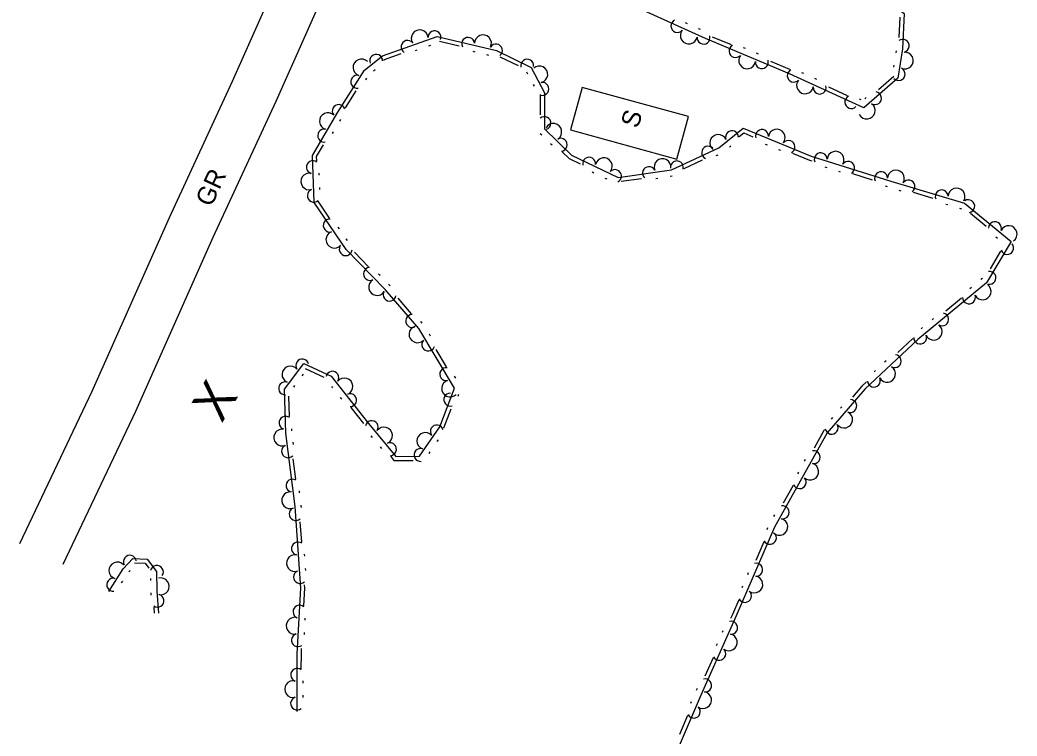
# Model space of a CAD drawing. Extents: x 2030130 to 2036320, y 723205 to 762423.
# Drawn here: x 2032510.8 to 2032711.2, y 760341.1 to 760485 of the extents above; entities that cross this region are included whole.
import ezdxf

# ---------------------------------------------------------------- set-up
doc = ezdxf.new("R2010")
doc.units = 0
for name, color, linetype in [('Draft_Station Labels Major', 7, 'Continuous'), ('Draft_Station Tics Major', 7, 'Continuous'), ('Exist Terrain Model Ground Surface', 7, 'Continuous'), ('Old_Level_23', 7, 'Continuous'), ('Old_Level_28', 7, 'Continuous')]:
    doc.layers.add(name, color=color, linetype=linetype)

msp = doc.modelspace()

# ---------------------------------------------------------------- linework, layer by layer
at = {"layer": 'Draft_Station Labels Major'}
for points in [[(2032510.76, 760379.73), (2032525.28, 760410.37), (2032540.81, 760445.33), (2032553.46, 760472.68), (2032565.25, 760499.26), (2032573.55, 760520.99), (2032582.53, 760547.1)], [(2032519.47, 760375.6), (2032534.05, 760406.34), (2032549.6, 760441.35), (2032562.24, 760468.7), (2032574.17, 760495.58), (2032582.62, 760517.7), (2032591.65, 760543.96)]]:
    msp.add_lwpolyline(points, dxfattribs=at)
at = {"layer": 'Draft_Station Tics Major'}
for points in [[(2032610.36, 760505.83), (2032617.7, 760509.06), (2032625.07, 760510.08), (2032635.55, 760509.05), (2032646.26, 760506.58), (2032658.84, 760502.68), (2032665.92, 760499.68), (2032681.91, 760491.35), (2032688.45, 760486.32), (2032688.15, 760479.19), (2032687.21, 760473.29), (2032680.34, 760467.34), (2032665.41, 760474.21), (2032648.54, 760481.27), (2032632.66, 760488.42), (2032618.48, 760493.45), (2032608.94, 760497.68), (2032607.53, 760501.46), (2032610.14, 760506.24)], [(2032687.6, 760485.58), (2032687.42, 760481.49)], [(2032644.9, 760484.26), (2032644.53, 760484.42)], [(2032647.52, 760483.08), (2032647.15, 760483.25)], [(2032566.45, 760345.97), (2032566.49, 760357.61), (2032567.18, 760370.77), (2032566.07, 760387.21), (2032564.19, 760401.97), (2032563.93, 760410.79), (2032567.82, 760415.97), (2032573.31, 760413.37), (2032580.84, 760403.88), (2032586.31, 760397.28), (2032591.09, 760397.29), (2032595.17, 760403.2), (2032598.11, 760411.01), (2032590.92, 760422.96), (2032584.18, 760430.79), (2032576.3, 760438.86), (2032569.87, 760448.28), (2032569.56, 760457.75), (2032574.67, 760466.46), (2032580.02, 760474.93), (2032583.62, 760477.8), (2032594.58, 760481.69), (2032606.53, 760478.85), (2032613.5, 760475.44), (2032616.15, 760470.39), (2032616.17, 760463.09), (2032621.61, 760457.81), (2032630.96, 760453.33), (2032641.69, 760454.86), (2032651.22, 760459.33), (2032656.11, 760463.24), (2032669.75, 760457.6), (2032685.78, 760452.57), (2032700.61, 760448.17), (2032709.97, 760440.49), (2032705.01, 760432.14), (2032691.24, 760420.8), (2032680.57, 760410.81), (2032673.01, 760402), (2032662.41, 760383.07), (2032654.73, 760365.19), (2032647.66, 760349.42), (2032642.43, 760337.21)], [(2032653.75, 760479.98), (2032649.96, 760481.56)], [(2032592.94, 760479.8), (2032593.33, 760479.94)], [(2032595.06, 760480.73), (2032599.05, 760479.78)], [(2032656.55, 760479.25), (2032656.18, 760479.41)], [(2032583.83, 760476.92), (2032584.02, 760477.07), (2032587.39, 760478.27)], [(2032590.24, 760478.84), (2032590.62, 760478.98)], [(2032601.75, 760478.72), (2032602.15, 760478.63)], [(2032604.54, 760478.06), (2032604.94, 760477.96)], [(2032607.18, 760477.62), (2032610.86, 760475.82)], [(2032659.2, 760478.14), (2032658.82, 760478.3)], [(2032686.84, 760478.78), (2032686.77, 760478.38)], [(2032581.84, 760474.8), (2032582.16, 760475.06)], [(2032665.47, 760475.07), (2032661.69, 760476.65)], [(2032686.39, 760475.95), (2032686.32, 760475.54)], [(2032580.24, 760472.98), (2032580.46, 760473.33)], [(2032612.57, 760474.57), (2032612.76, 760474.21)], [(2032668.28, 760474.24), (2032667.91, 760474.41)], [(2032670.89, 760473.04), (2032670.52, 760473.21)], [(2032686.39, 760473.66), (2032683.29, 760470.98)], [(2032613.9, 760472.03), (2032614.09, 760471.67)], [(2032677.05, 760469.75), (2032673.33, 760471.47)], [(2032576.17, 760467.31), (2032578.36, 760470.77)], [(2032615.33, 760470.01), (2032615.34, 760465.91)], [(2032679.83, 760468.93), (2032679.46, 760469.1)], [(2032680.85, 760469.41), (2032680.54, 760469.14)], [(2032575.04, 760464.67), (2032575.25, 760465.03)], [(2032573.59, 760462.2), (2032573.8, 760462.55)], [(2032615.34, 760462.17), (2032615.64, 760461.89)], [(2032655.33, 760461.57), (2032656.24, 760462.3), (2032658.06, 760461.54)], [(2032570.42, 760456.68), (2032570.39, 760457.54), (2032571.79, 760459.93)], [(2032617.4, 760460.18), (2032617.7, 760459.89)], [(2032653.34, 760459.45), (2032653.66, 760459.71)], [(2032660.55, 760460.07), (2032660.93, 760459.91)], [(2032619.75, 760458.47), (2032621.13, 760457.13), (2032623.33, 760456.07)], [(2032650.71, 760457.74), (2032651.09, 760457.91)], [(2032663.21, 760458.97), (2032663.59, 760458.82)], [(2032666.02, 760458.25), (2032669.47, 760456.83), (2032669.89, 760456.7)], [(2032644.23, 760455.15), (2032647.94, 760456.89)], [(2032672.5, 760455.45), (2032672.89, 760455.32)], [(2032570.92, 760453.82), (2032570.91, 760454.23)], [(2032625.74, 760454.46), (2032626.11, 760454.29)], [(2032628.33, 760453.22), (2032628.7, 760453.04)], [(2032631.62, 760452.59), (2032635.68, 760453.17)], [(2032638.58, 760453.17), (2032638.98, 760453.23)], [(2032641.42, 760453.58), (2032641.82, 760453.64)], [(2032675.24, 760454.59), (2032675.63, 760454.46)], [(2032678.1, 760454.12), (2032682.02, 760452.89)], [(2032571.01, 760450.95), (2032571, 760451.36)], [(2032684.63, 760451.64), (2032685.03, 760451.52)], [(2032687.4, 760450.81), (2032687.79, 760450.69)], [(2032690.27, 760450.38), (2032694.2, 760449.21)], [(2032572.99, 760445.16), (2032570.68, 760448.55)], [(2032696.84, 760448), (2032697.23, 760447.89)], [(2032699.59, 760447.19), (2032699.98, 760447.07)], [(2032701.77, 760446.16), (2032704.94, 760443.56)], [(2032574.95, 760443.02), (2032574.72, 760443.36)], [(2032576.57, 760440.66), (2032576.34, 760440.99)], [(2032706.89, 760441.42), (2032707.21, 760441.16)], [(2032580.83, 760435.4), (2032577.97, 760438.33)], [(2032707.84, 760438.52), (2032705.75, 760434.99)], [(2032583.13, 760433.63), (2032582.85, 760433.92)], [(2032704.2, 760433.06), (2032703.88, 760432.8)], [(2032585.19, 760431.51), (2032585.09, 760431.62), (2032584.85, 760431.87)], [(2032701.98, 760431.24), (2032701.66, 760430.98)], [(2032589.42, 760425.96), (2032586.75, 760429.07)], [(2032700.02, 760429.1), (2032696.86, 760426.49)], [(2032694.38, 760424.98), (2032694.06, 760424.72)], [(2032591.6, 760424.05), (2032591.33, 760424.36)], [(2032692.16, 760423.16), (2032691.85, 760422.9)], [(2032593.26, 760421.46), (2032593.04, 760421.82)], [(2032690.2, 760420.95), (2032687.2, 760418.15)], [(2032596.5, 760415.28), (2032594.39, 760418.79)], [(2032568.1, 760414.93), (2032571.81, 760413.17)], [(2032684.83, 760416.48), (2032684.53, 760416.2)], [(2032567.5, 760413.49), (2032567.75, 760413.82)], [(2032598.33, 760413.03), (2032598.12, 760413.38)], [(2032682.73, 760414.52), (2032682.43, 760414.24)], [(2032565.77, 760411.2), (2032566.02, 760411.52)], [(2032573.34, 760411.35), (2032573.6, 760411.03)], [(2032680.92, 760412.26), (2032679.98, 760411.38), (2032678.09, 760409.18)], [(2032564.91, 760405.28), (2032564.79, 760409.38)], [(2032575.13, 760409.1), (2032575.38, 760408.78)], [(2032598.82, 760409.4), (2032598.97, 760409.79)], [(2032577.23, 760407.11), (2032579.78, 760403.9)], [(2032675.91, 760407.26), (2032675.64, 760406.95)], [(2032595.98, 760403.02), (2032597.43, 760406.86)], [(2032674.04, 760405.08), (2032673.77, 760404.77)], [(2032565.41, 760402.42), (2032565.4, 760402.83)], [(2032581.3, 760401.4), (2032581.56, 760401.09)], [(2032672.48, 760402.64), (2032672.34, 760402.47), (2032670.36, 760398.94)], [(2032565.72, 760399.69), (2032565.67, 760400.1)], [(2032583.13, 760399.19), (2032583.39, 760398.88)], [(2032594.62, 760400.24), (2032594.85, 760400.57)], [(2032585.27, 760397.24), (2032585.92, 760396.46), (2032589.78, 760396.47)], [(2032592.99, 760397.88), (2032593.22, 760398.21)], [(2032566.19, 760392.72), (2032565.67, 760396.79)], [(2032668.6, 760396.64), (2032668.4, 760396.28)], [(2032667.2, 760394.13), (2032667, 760393.78)], [(2032666.15, 760391.43), (2032664.15, 760387.85)], [(2032566.96, 760389.93), (2032566.91, 760390.33)], [(2032567.31, 760387), (2032567.29, 760387.33), (2032567.27, 760387.48)], [(2032662.39, 760385.55), (2032662.19, 760385.19)], [(2032567.38, 760380.02), (2032567.1, 760384.11)], [(2032661, 760382.89), (2032660.84, 760382.52)], [(2032660.24, 760380.09), (2032658.62, 760376.33)], [(2032567.98, 760377.19), (2032567.95, 760377.59)], [(2032528.61, 760370.08), (2032531.52, 760374.65), (2032533.42, 760376.73), (2032536.31, 760376.58), (2032538.17, 760374.16), (2032538.27, 760370.19), (2032538.57, 760365.78)], [(2032533.75, 760375.89), (2032535.89, 760375.78), (2032536.63, 760374.83)], [(2032532.65, 760374.06), (2032532.92, 760374.36)], [(2032568.18, 760374.32), (2032568.15, 760374.73)], [(2032657.11, 760373.85), (2032656.95, 760373.47)], [(2032531.19, 760371.84), (2032531.41, 760372.19)], [(2032536.98, 760372.73), (2032536.98, 760372.32)], [(2032567.82, 760367.24), (2032568.01, 760370.78), (2032567.96, 760371.43)], [(2032655.98, 760371.21), (2032655.82, 760370.84)], [(2032537.06, 760369.81), (2032537.09, 760369.4)], [(2032537.67, 760366.97), (2032537.75, 760365.73)], [(2032655.22, 760368.41), (2032653.98, 760365.52), (2032653.59, 760364.66)], [(2032568.08, 760364.35), (2032568.1, 760364.76)], [(2032567.93, 760361.48), (2032567.95, 760361.89)], [(2032652.04, 760362.21), (2032651.88, 760361.84)], [(2032650.87, 760359.59), (2032650.7, 760359.22)], [(2032567.3, 760354.58), (2032567.31, 760357.58), (2032567.37, 760358.63)], [(2032650.07, 760356.8), (2032648.39, 760353.06)], [(2032567.7, 760351.71), (2032567.7, 760352.12)], [(2032567.69, 760348.83), (2032567.69, 760349.24)], [(2032646.84, 760350.61), (2032646.67, 760350.24)], [(2032645.69, 760347.96), (2032645.53, 760347.58)], [(2032644.94, 760345.16), (2032643.32, 760341.39)]]:
    msp.add_lwpolyline(points, dxfattribs=at)
for centre, radius, start, end in [((2032642.9, 760483.81), 1.3, 116.5457, 317.3422), ((2032591.09, 760481.32), 1.69, 5.5089, 213.5814), ((2032594.07, 760481.51), 1.3, 340.3136, 181.1102), ((2032600.84, 760480.2), 1.3, 5.0446, 205.8411), ((2032603.82, 760480.33), 1.69, 332.5734, 180.6459), ((2032645.18, 760481.88), 1.69, 141.7409, 349.8134), ((2032648.14, 760481.45), 1.3, 174.2121, 15.0087), ((2032688.17, 760479.81), 1.3, 285.9923, 126.7889), ((2032588.66, 760479.59), 1.3, 37.9801, 238.7766), ((2032606.42, 760478.87), 1.3, 307.3781, 148.1747), ((2032654.57, 760478.75), 1.3, 118.0443, 318.8408), ((2032579.39, 760475.46), 1.69, 43.6576, 251.7301), ((2032582.35, 760476.79), 1.3, 359.3518, 200.1483), ((2032612.7, 760475.83), 1.3, 352.3845, 193.181), ((2032656.9, 760476.88), 1.69, 143.2395, 351.312), ((2032688.6, 760476.84), 1.69, 246.9776, 95.0501), ((2032615.14, 760474.07), 1.69, 283.6094, 131.6819), ((2032659.86, 760476.53), 1.3, 175.7107, 16.5073), ((2032687.35, 760474.13), 1.3, 221.7824, 62.5789), ((2032578.55, 760472.6), 1.3, 76.1288, 276.9254), ((2032666.28, 760473.81), 1.3, 116.0688, 316.8654), ((2032615.75, 760471.15), 1.3, 258.4141, 99.2107), ((2032668.54, 760471.86), 1.69, 141.2641, 349.3366), ((2032671.49, 760471.41), 1.3, 173.7353, 14.5318), ((2032677.83, 760468.49), 1.3, 116.0688, 316.8654), ((2032682.59, 760469.28), 1.3, 239.3626, 80.1592), ((2032574.82, 760466.7), 1.3, 18.4624, 219.2589), ((2032680.96, 760466.78), 1.69, 206.8914, 54.9639), ((2032572.65, 760464.65), 1.69, 45.583, 253.6555), ((2032616.16, 760464.27), 1.3, 288.5765, 129.3731), ((2032571.91, 760461.76), 1.3, 78.0542, 278.8507), ((2032617.95, 760462.5), 1.69, 301.8272, 149.8997), ((2032662.85, 760461.34), 1.69, 323.5048, 171.5773), ((2032619.43, 760459.92), 1.3, 276.632, 117.4285), ((2032651.1, 760460.29), 1.69, 24.5896, 232.662), ((2032653.86, 760461.44), 1.3, 359.3943, 200.1909), ((2032659.89, 760461.68), 1.3, 355.976, 196.7726), ((2032649.08, 760458.33), 1.3, 43.58, 244.3766), ((2032665.19, 760459.48), 1.3, 298.3095, 139.1061), ((2032625.16, 760456.1), 1.3, 352.8281, 193.6247), ((2032628.11, 760455.6), 1.69, 320.3569, 168.4294), ((2032639.91, 760455.43), 1.69, 354.1043, 202.1768), ((2032671.7, 760456.99), 1.3, 1.0155, 201.8121), ((2032674.68, 760456.91), 1.69, 328.5443, 176.6168), ((2032569.64, 760455.42), 1.3, 52.6182, 253.4147), ((2032637.18, 760454.21), 1.3, 26.5755, 227.372), ((2032642.77, 760455.36), 1.3, 345.9135, 186.7101), ((2032677.18, 760455.27), 1.3, 303.349, 144.1456), ((2032568.91, 760452.53), 1.69, 77.8134, 285.8859), ((2032630.34, 760453.62), 1.3, 295.1616, 135.9582), ((2032683.83, 760453.18), 1.3, 1.0155, 201.8121), ((2032686.8, 760453.12), 1.69, 329.4323, 177.5048), ((2032689.32, 760451.52), 1.3, 304.2371, 145.0336), ((2032698.99, 760449.5), 1.69, 329.4323, 177.5048), ((2032569.82, 760449.68), 1.3, 110.2846, 311.0812), ((2032696.01, 760449.53), 1.3, 1.9035, 202.7001), ((2032701.34, 760447.57), 1.3, 281.3736, 122.1702), ((2032573.01, 760443.68), 1.3, 85.1293, 285.9259), ((2032706.72, 760443.15), 1.3, 339.0401, 179.8366), ((2032709.46, 760441.96), 1.69, 306.5689, 154.6414), ((2032573.95, 760440.85), 1.69, 110.3246, 318.3971), ((2032576.23, 760438.93), 1.3, 152.7484, 353.545), ((2032709.17, 760439.16), 1.3, 200.0628, 40.8593), ((2032581.11, 760433.95), 1.3, 95.082, 295.8785), ((2032705.62, 760433.16), 1.3, 257.7292, 98.5258), ((2032582.52, 760431.32), 1.69, 120.2772, 328.3497), ((2032704.23, 760430.44), 1.69, 205.4318, 53.5043), ((2032585.05, 760429.78), 1.3, 149.131, 349.9275), ((2032701.49, 760429.24), 1.3, 180.2365, 21.0331), ((2032589.6, 760424.49), 1.3, 91.4645, 292.2611), ((2032696.11, 760424.81), 1.3, 237.903, 78.6996), ((2032590.65, 760421.81), 1.69, 106.9986, 315.0711), ((2032694.42, 760422.35), 1.69, 205.4318, 53.5043), ((2032691.68, 760421.16), 1.3, 180.2365, 21.0331), ((2032592.84, 760419.77), 1.3, 139.4698, 340.2664), ((2032686.57, 760416.43), 1.3, 241.5437, 82.3402), ((2032565.12, 760413.74), 1.69, 38.9822, 247.0547), ((2032567.5, 760415.54), 1.3, 13.7869, 214.5835), ((2032596.43, 760413.8), 1.3, 81.8033, 282.5999), ((2032685.03, 760413.87), 1.69, 209.0725, 57.145), ((2032573.54, 760413.08), 1.3, 326.8681, 167.6647), ((2032575.97, 760411.34), 1.69, 294.3969, 142.4694), ((2032682.38, 760412.5), 1.3, 183.8772, 24.6738), ((2032564.05, 760410.95), 1.3, 71.4534, 272.25), ((2032597.21, 760410.92), 1.69, 106.9986, 315.0711), ((2032577.11, 760408.58), 1.3, 269.2016, 109.9982), ((2032597.24, 760408.69), 1.3, 87.817, 288.6135), ((2032677.64, 760407.4), 1.3, 247.8293, 88.6258), ((2032564.13, 760404.03), 1.3, 52.489, 253.2856), ((2032676.4, 760404.68), 1.69, 215.3581, 63.4306), ((2032581.46, 760403.14), 1.3, 328.0601, 168.8566), ((2032583.92, 760401.45), 1.69, 295.5889, 143.6614), ((2032594.54, 760402.29), 1.3, 16.1156, 216.9122), ((2032673.9, 760403.04), 1.3, 190.1628, 30.9594), ((2032563.48, 760401.06), 1.69, 83.2083, 291.2808), ((2032592.23, 760400.39), 1.69, 41.3109, 249.3833), ((2032564.65, 760398.31), 1.3, 115.6795, 316.4761), ((2032585.12, 760398.71), 1.3, 270.3936, 111.1902), ((2032591.28, 760397.56), 1.3, 73.782, 274.5786), ((2032670.28, 760397.11), 1.3, 259.1836, 99.9802), ((2032669.59, 760394.2), 1.69, 226.7124, 74.7849), ((2032667.47, 760392.1), 1.3, 201.5172, 42.3137), ((2032565.53, 760391.4), 1.3, 58.013, 258.8096), ((2032565.08, 760388.45), 1.69, 83.2083, 291.2808), ((2032566.17, 760385.69), 1.3, 112.323, 313.1196), ((2032664.06, 760386.02), 1.3, 259.1836, 99.9802), ((2032663.38, 760383.11), 1.69, 226.7124, 74.7849), ((2032661.48, 760380.9), 1.3, 207.5153, 48.3119), ((2032566.64, 760378.74), 1.3, 54.6566, 255.4531), ((2032532.84, 760376.1), 1.3, 8.2866, 209.0832), ((2032566.02, 760375.82), 1.69, 79.8518, 287.9243), ((2032530.34, 760374.33), 1.69, 43.4799, 251.5524), ((2032538.28, 760374.03), 1.3, 326.0017, 166.7982), ((2032658.73, 760374.49), 1.3, 265.1818, 105.9784), ((2032567.03, 760373.01), 1.3, 112.323, 313.1196), ((2032658.35, 760371.53), 1.69, 232.7106, 80.7831), ((2032529.49, 760371.47), 1.3, 75.9511, 276.7477), ((2032539.06, 760371.14), 1.69, 257.2993, 105.3718), ((2032538.4, 760368.26), 1.3, 234.7305, 75.5271), ((2032656.46, 760369.22), 1.3, 207.5153, 48.3119), ((2032566.94, 760366.05), 1.3, 47.7628, 248.5594), ((2032565.97, 760363.23), 1.69, 72.9581, 281.0306), ((2032653.67, 760362.83), 1.3, 264.279, 105.0755), ((2032566.63, 760360.32), 1.3, 105.4293, 306.2259), ((2032653.24, 760359.88), 1.69, 231.8078, 79.8803), ((2032651.32, 760357.59), 1.3, 206.6125, 47.4091), ((2032566.48, 760353.35), 1.3, 50.5747, 251.3713), ((2032565.65, 760350.48), 1.69, 75.77, 283.8424), ((2032648.47, 760351.23), 1.3, 264.279, 105.0755), ((2032566.46, 760347.61), 1.3, 108.2412, 309.0377), ((2032648.06, 760348.28), 1.69, 232.7824, 80.8548), ((2032646.18, 760345.97), 1.3, 207.5871, 48.3837)]:
    msp.add_arc(centre, radius, start, end, dxfattribs=at)
at = {"layer": 'Exist Terrain Model Ground Surface'}
msp.add_lwpolyline([(2032642.8, 760457.04), (2032645.14, 760465.6), (2032623.75, 760471.45), (2032621.41, 760462.89)], close=True, dxfattribs=at)

# ---------------------------------------------------------------- texts
at = {"layer": 'Draft_Station Tics Major'}
msp.add_text('X', height=7.38, rotation=58.9267, dxfattribs=at).set_placement((2032551.3, 760403.8))
at = {"layer": 'Old_Level_23'}
msp.add_text('GR', height=3.691, rotation=65.1853, dxfattribs=at).set_placement((2032549.22, 760447.24))
at = {"layer": 'Old_Level_28'}
msp.add_text('S', height=3.69, rotation=71.2023, dxfattribs=at).set_placement((2032634.89, 760463.04))

doc.saveas('drawing.dxf')
